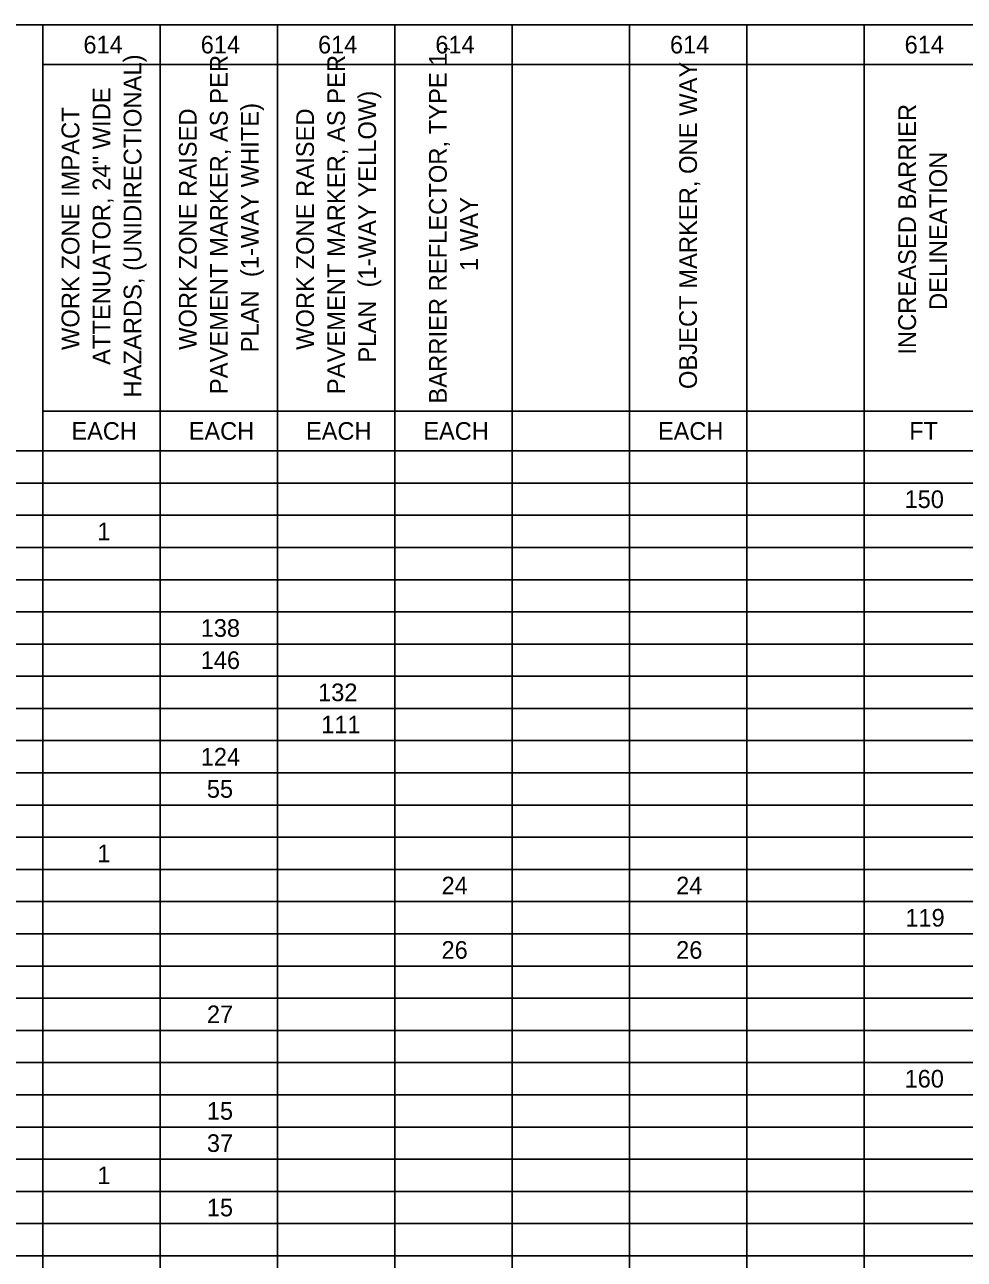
# Model space of a CAD drawing. Extents: x 91011267 to 91022583, y 37007614 to 37014266.
# Drawn here: x 91011643 to 91012044, y 37010699 to 37011225 of the extents above; entities that cross this region are included whole.
import ezdxf

# ---------------------------------------------------------------- set-up
doc = ezdxf.new("R2010")
doc.units = 0
doc.layers.add('SC_Scratch2', color=7, linetype='Continuous')
doc.layers.add('SH_Data', color=7, linetype='Continuous')

msp = doc.modelspace()

# ---------------------------------------------------------------- linework, layer by layer
at = {"layer": 'SC_Scratch2'}
msp.add_lwpolyline([(91011277.35, 37011225.45), (91012802.35, 37011225.45), (91012802.35, 37010175.45), (91011277.35, 37010175.45)], close=True, dxfattribs=at)
at = {"layer": 'SH_Data'}
for p, q in [((91011596.32, 37011225.45), (91011650.36, 37011225.45)), ((91011650.36, 37011225.45), (91011950.88, 37011225.45)), ((91011650.36, 37011225.45), (91011650.36, 37011134.52)), ((91011700.45, 37011225.45), (91011700.45, 37011134.52)), ((91011750.54, 37011225.45), (91011750.54, 37011134.52)), ((91011800.62, 37011225.45), (91011800.62, 37011134.52)), ((91011850.71, 37011225.45), (91011850.71, 37011134.52)), ((91011900.79, 37011225.45), (91011900.79, 37011134.52)), ((91011950.88, 37011225.45), (91012000.97, 37011225.45)), ((91011950.88, 37011225.45), (91011950.88, 37011134.52)), ((91012000.97, 37011225.45), (91012551.92, 37011225.45)), ((91012000.97, 37011225.45), (91012000.97, 37011134.52)), ((91011650.36, 37011208.44), (91011950.88, 37011208.44)), ((91011950.88, 37011208.44), (91012000.97, 37011208.44)), ((91012000.97, 37011208.44), (91012551.92, 37011208.44)), ((91011650.36, 37011134.52), (91011650.36, 37011060.59)), ((91011700.45, 37011134.52), (91011700.45, 37011060.59)), ((91011750.54, 37011134.52), (91011750.54, 37011060.59)), ((91011800.62, 37011134.52), (91011800.62, 37011060.59)), ((91011850.71, 37011134.52), (91011850.71, 37011060.59)), ((91011900.79, 37011134.52), (91011900.79, 37011060.59)), ((91011950.88, 37011134.52), (91011950.88, 37011060.59)), ((91012000.97, 37011134.52), (91012000.97, 37011060.59)), ((91011650.36, 37011060.59), (91011950.88, 37011060.59)), ((91011650.36, 37011060.59), (91011650.36, 37011043.58)), ((91011700.45, 37011060.59), (91011700.45, 37011043.58)), ((91011750.54, 37011060.59), (91011750.54, 37011043.58)), ((91011800.62, 37011060.59), (91011800.62, 37011043.58)), ((91011850.71, 37011060.59), (91011850.71, 37011043.58)), ((91011900.79, 37011060.59), (91011900.79, 37011043.58)), ((91011950.88, 37011060.59), (91012000.97, 37011060.59)), ((91011950.88, 37011060.59), (91011950.88, 37011043.58)), ((91012000.97, 37011060.59), (91012551.92, 37011060.59)), ((91012000.97, 37011060.59), (91012000.97, 37011043.58)), ((91011596.32, 37011043.58), (91011650.36, 37011043.58)), ((91011650.36, 37011043.58), (91011950.88, 37011043.58)), ((91011650.36, 37011043.58), (91011650.36, 37010933.68)), ((91011700.45, 37011043.58), (91011700.45, 37010933.68)), ((91011750.54, 37011043.58), (91011750.54, 37010933.68)), ((91011800.62, 37011043.58), (91011800.62, 37010933.68)), ((91011850.71, 37011043.58), (91011850.71, 37010933.68)), ((91011900.79, 37011043.58), (91011900.79, 37010933.68)), ((91011950.88, 37011043.58), (91012000.97, 37011043.58)), ((91011950.88, 37011043.58), (91011950.88, 37010933.68)), ((91012000.97, 37011043.58), (91012551.92, 37011043.58)), ((91012000.97, 37011043.58), (91012000.97, 37010933.68)), ((91011596.32, 37011029.85), (91011650.36, 37011029.85)), ((91011650.36, 37011029.85), (91011950.88, 37011029.85)), ((91011950.88, 37011029.85), (91012000.97, 37011029.85)), ((91012000.97, 37011029.85), (91012551.92, 37011029.85)), ((91011596.32, 37011016.11), (91011650.36, 37011016.11)), ((91011650.36, 37011016.11), (91011950.88, 37011016.11)), ((91011950.88, 37011016.11), (91012000.97, 37011016.11)), ((91012000.97, 37011016.11), (91012551.92, 37011016.11)), ((91011596.32, 37011002.37), (91011650.36, 37011002.37)), ((91011650.36, 37011002.37), (91011950.88, 37011002.37)), ((91011950.88, 37011002.37), (91012000.97, 37011002.37)), ((91012000.97, 37011002.37), (91012551.92, 37011002.37)), ((91011596.32, 37010988.63), (91011650.36, 37010988.63)), ((91011650.36, 37010988.63), (91011950.88, 37010988.63)), ((91011950.88, 37010988.63), (91012000.97, 37010988.63)), ((91012000.97, 37010988.63), (91012551.92, 37010988.63)), ((91011596.32, 37010974.89), (91011650.36, 37010974.89)), ((91011650.36, 37010974.89), (91011950.88, 37010974.89)), ((91011950.88, 37010974.89), (91012000.97, 37010974.89)), ((91012000.97, 37010974.89), (91012551.92, 37010974.89)), ((91011596.32, 37010961.15), (91011650.36, 37010961.15)), ((91011650.36, 37010961.15), (91011950.88, 37010961.15)), ((91011950.88, 37010961.15), (91012000.97, 37010961.15)), ((91012000.97, 37010961.15), (91012551.92, 37010961.15)), ((91011596.32, 37010947.42), (91011650.36, 37010947.42)), ((91011650.36, 37010947.42), (91011950.88, 37010947.42)), ((91011950.88, 37010947.42), (91012000.97, 37010947.42)), ((91012000.97, 37010947.42), (91012551.92, 37010947.42)), ((91011596.32, 37010933.68), (91011650.36, 37010933.68)), ((91011650.36, 37010933.68), (91011950.88, 37010933.68)), ((91011650.36, 37010933.68), (91011650.36, 37010919.94)), ((91011700.45, 37010933.68), (91011700.45, 37010919.94)), ((91011750.54, 37010933.68), (91011750.54, 37010919.94)), ((91011800.62, 37010933.68), (91011800.62, 37010919.94)), ((91011850.71, 37010933.68), (91011850.71, 37010919.94)), ((91011900.79, 37010933.68), (91011900.79, 37010919.94)), ((91011950.88, 37010933.68), (91012000.97, 37010933.68)), ((91011950.88, 37010933.68), (91011950.88, 37010919.94)), ((91012000.97, 37010933.68), (91012551.92, 37010933.68)), ((91012000.97, 37010933.68), (91012000.97, 37010919.94)), ((91011596.32, 37010919.94), (91011650.36, 37010919.94)), ((91011650.36, 37010919.94), (91011950.88, 37010919.94)), ((91011650.36, 37010919.94), (91011650.36, 37010892.46)), ((91011700.45, 37010919.94), (91011700.45, 37010892.46)), ((91011750.54, 37010919.94), (91011750.54, 37010892.46)), ((91011800.62, 37010919.94), (91011800.62, 37010892.46)), ((91011850.71, 37010919.94), (91011850.71, 37010892.46)), ((91011900.79, 37010919.94), (91011900.79, 37010892.46)), ((91011950.88, 37010919.94), (91012000.97, 37010919.94)), ((91011950.88, 37010919.94), (91011950.88, 37010892.46)), ((91012000.97, 37010919.94), (91012551.92, 37010919.94)), ((91012000.97, 37010919.94), (91012000.97, 37010892.46)), ((91011596.32, 37010906.2), (91011650.36, 37010906.2)), ((91011650.36, 37010906.2), (91011950.88, 37010906.2)), ((91011950.88, 37010906.2), (91012000.97, 37010906.2)), ((91012000.97, 37010906.2), (91012551.92, 37010906.2)), ((91011596.32, 37010892.46), (91011650.36, 37010892.46)), ((91011650.36, 37010892.46), (91011950.88, 37010892.46)), ((91011650.36, 37010892.46), (91011650.36, 37010878.72)), ((91011700.45, 37010892.46), (91011700.45, 37010878.72)), ((91011750.54, 37010892.46), (91011750.54, 37010878.72)), ((91011800.62, 37010892.46), (91011800.62, 37010878.72)), ((91011850.71, 37010892.46), (91011850.71, 37010878.72)), ((91011900.79, 37010892.46), (91011900.79, 37010878.72)), ((91011950.88, 37010892.46), (91012000.97, 37010892.46)), ((91011950.88, 37010892.46), (91011950.88, 37010878.72)), ((91012000.97, 37010892.46), (91012551.92, 37010892.46)), ((91012000.97, 37010892.46), (91012000.97, 37010878.72)), ((91011596.32, 37010878.72), (91011650.36, 37010878.72)), ((91011650.36, 37010878.72), (91011950.88, 37010878.72)), ((91011650.36, 37010878.72), (91011650.36, 37010864.99)), ((91011700.45, 37010878.72), (91011700.45, 37010864.99)), ((91011750.54, 37010878.72), (91011750.54, 37010864.99)), ((91011800.62, 37010878.72), (91011800.62, 37010864.99)), ((91011850.71, 37010878.72), (91011850.71, 37010864.99)), ((91011900.79, 37010878.72), (91011900.79, 37010864.99)), ((91011950.88, 37010878.72), (91012000.97, 37010878.72)), ((91011950.88, 37010878.72), (91011950.88, 37010864.99)), ((91012000.97, 37010878.72), (91012551.92, 37010878.72)), ((91012000.97, 37010878.72), (91012000.97, 37010864.99)), ((91011596.32, 37010864.99), (91011650.36, 37010864.99)), ((91011650.36, 37010864.99), (91011950.88, 37010864.99)), ((91011650.36, 37010864.99), (91011650.36, 37010851.25)), ((91011700.45, 37010864.99), (91011700.45, 37010851.25)), ((91011750.54, 37010864.99), (91011750.54, 37010851.25)), ((91011800.62, 37010864.99), (91011800.62, 37010851.25)), ((91011850.71, 37010864.99), (91011850.71, 37010851.25)), ((91011900.79, 37010864.99), (91011900.79, 37010851.25)), ((91011950.88, 37010864.99), (91012000.97, 37010864.99)), ((91011950.88, 37010864.99), (91011950.88, 37010851.25)), ((91012000.97, 37010864.99), (91012551.92, 37010864.99)), ((91012000.97, 37010864.99), (91012000.97, 37010851.25)), ((91011596.32, 37010851.25), (91011650.36, 37010851.25)), ((91011650.36, 37010851.25), (91011950.88, 37010851.25)), ((91011650.36, 37010851.25), (91011650.36, 37010645.17)), ((91011700.45, 37010851.25), (91011700.45, 37010645.17)), ((91011750.54, 37010851.25), (91011750.54, 37010645.17)), ((91011800.62, 37010851.25), (91011800.62, 37010645.17)), ((91011850.71, 37010851.25), (91011850.71, 37010645.17)), ((91011900.79, 37010851.25), (91011900.79, 37010645.17)), ((91011950.88, 37010851.25), (91012000.97, 37010851.25)), ((91011950.88, 37010851.25), (91011950.88, 37010645.17)), ((91012000.97, 37010851.25), (91012551.92, 37010851.25)), ((91012000.97, 37010851.25), (91012000.97, 37010645.17)), ((91011596.32, 37010837.51), (91011650.36, 37010837.51)), ((91011650.36, 37010837.51), (91011950.88, 37010837.51)), ((91011950.88, 37010837.51), (91012000.97, 37010837.51)), ((91012000.97, 37010837.51), (91012551.92, 37010837.51)), ((91011596.32, 37010823.77), (91011650.36, 37010823.77)), ((91011650.36, 37010823.77), (91011950.88, 37010823.77)), ((91011950.88, 37010823.77), (91012000.97, 37010823.77)), ((91012000.97, 37010823.77), (91012551.92, 37010823.77)), ((91011596.32, 37010810.03), (91011650.36, 37010810.03)), ((91011650.36, 37010810.03), (91011950.88, 37010810.03)), ((91011950.88, 37010810.03), (91012000.97, 37010810.03)), ((91012000.97, 37010810.03), (91012551.92, 37010810.03)), ((91011596.32, 37010796.29), (91011650.36, 37010796.29)), ((91011650.36, 37010796.29), (91011950.88, 37010796.29)), ((91011950.88, 37010796.29), (91012000.97, 37010796.29)), ((91012000.97, 37010796.29), (91012551.92, 37010796.29)), ((91011596.32, 37010782.56), (91011650.36, 37010782.56)), ((91011650.36, 37010782.56), (91011950.88, 37010782.56)), ((91011950.88, 37010782.56), (91012000.97, 37010782.56)), ((91012000.97, 37010782.56), (91012551.92, 37010782.56)), ((91011596.32, 37010768.82), (91011650.36, 37010768.82)), ((91011650.36, 37010768.82), (91011950.88, 37010768.82)), ((91011950.88, 37010768.82), (91012000.97, 37010768.82)), ((91012000.97, 37010768.82), (91012551.92, 37010768.82)), ((91011596.32, 37010755.08), (91011650.36, 37010755.08)), ((91011650.36, 37010755.08), (91011950.88, 37010755.08)), ((91011950.88, 37010755.08), (91012000.97, 37010755.08)), ((91012000.97, 37010755.08), (91012551.92, 37010755.08)), ((91011596.32, 37010741.34), (91011650.36, 37010741.34)), ((91011650.36, 37010741.34), (91011950.88, 37010741.34)), ((91011950.88, 37010741.34), (91012000.97, 37010741.34)), ((91012000.97, 37010741.34), (91012551.92, 37010741.34)), ((91011596.32, 37010727.6), (91011650.36, 37010727.6)), ((91011650.36, 37010727.6), (91011950.88, 37010727.6)), ((91011950.88, 37010727.6), (91012000.97, 37010727.6)), ((91012000.97, 37010727.6), (91012551.92, 37010727.6)), ((91011596.32, 37010713.86), (91011650.36, 37010713.86)), ((91011650.36, 37010713.86), (91011950.88, 37010713.86)), ((91011950.88, 37010713.86), (91012000.97, 37010713.86)), ((91012000.97, 37010713.86), (91012551.92, 37010713.86)), ((91011596.32, 37010700.13), (91011650.36, 37010700.13)), ((91011650.36, 37010700.13), (91011950.88, 37010700.13)), ((91011950.88, 37010700.13), (91012000.97, 37010700.13)), ((91012000.97, 37010700.13), (91012551.92, 37010700.13))]:
    msp.add_line(p, q, dxfattribs=at)

# ---------------------------------------------------------------- texts
for s, height, p in [('614', 7.523, (91011667.69, 37011213.19)), ('614', 7.523, (91011717.78, 37011213.19)), ('614', 7.523, (91011767.86, 37011213.19)), ('614', 7.523, (91011817.95, 37011213.19)), ('614', 7.523, (91011918.12, 37011213.19)), ('614', 7.523, (91012018.3, 37011213.19)), ('EACH', 7.523, (91011662.55, 37011048.33)), ('EACH', 7.523, (91011712.64, 37011048.33)), ('EACH', 7.523, (91011762.72, 37011048.33)), ('EACH', 7.523, (91011812.81, 37011048.33)), ('EACH', 7.523, (91011912.98, 37011048.33)), ('FT', 7.523, (91012020.28, 37011048.33)), ('150', 7.523, (91012018.29, 37011019.21)), ('1', 7.52, (91011673.63, 37011005.48)), ('138', 7.523, (91011717.76, 37010964.26)), ('146', 7.523, (91011717.76, 37010950.52)), ('132', 7.523, (91011767.88, 37010936.79)), ('111', 7.523, (91011769.21, 37010923.05)), ('124', 7.523, (91011717.78, 37010909.31)), ('55', 7.523, (91011720.38, 37010895.57)), ('1', 7.52, (91011673.63, 37010868.09)), ('24', 7.523, (91011820.6, 37010854.36)), ('24', 7.523, (91011920.77, 37010854.36)), ('119', 7.523, (91012018.63, 37010840.62)), ('26', 7.523, (91011820.58, 37010826.88)), ('26', 7.523, (91011920.76, 37010826.88)), ('27', 7.523, (91011720.41, 37010799.4)), ('160', 7.523, (91012018.29, 37010771.93)), ('15', 7.523, (91011720.38, 37010758.19)), ('37', 7.523, (91011720.41, 37010744.45)), ('1', 7.52, (91011673.63, 37010730.71)), ('15', 7.523, (91011720.38, 37010716.97))]:
    msp.add_text(s, height=height, dxfattribs=at).set_placement(p)
for s, height, p in [('HAZARDS, (UNIDIRECTIONAL)', 7.5789, (91011692.46, 37011066.36)), ('PAVEMENT MARKER, AS PER ', 7.5789, (91011729.28, 37011067.81)), ('PAVEMENT MARKER, AS PER ', 7.5789, (91011779.37, 37011067.81)), ('BARRIER REFLECTOR, TYPE 1, ', 7.5789, (91011822.82, 37011063.79)), ('OBJECT MARKER, ONE WAY', 7.5789, (91011929.63, 37011069.98)), ('ATTENUATOR, 24" WIDE ', 7.5789, (91011679.19, 37011080.26)), ('PLAN  (1-WAY YELLOW)', 7.5789, (91011792.63, 37011081.25)), ('WORK ZONE IMPACT ', 7.5789, (91011665.93, 37011086.61)), ('PLAN  (1-WAY WHITE)', 7.5789, (91011742.54, 37011085.64)), ('INCREASED BARRIER ', 7.5789, (91012023.17, 37011084.64)), ('WORK ZONE RAISED ', 7.5789, (91011716.02, 37011086.67)), ('WORK ZONE RAISED ', 7.5789, (91011766.1, 37011086.67)), ('DELINEATION', 7.5789, (91012036.43, 37011103.71)), ('1 WAY', 7.579, (91011836.09, 37011120.36))]:
    msp.add_text(s, height=height, rotation=90, dxfattribs=at).set_placement(p)

doc.saveas('drawing.dxf')
